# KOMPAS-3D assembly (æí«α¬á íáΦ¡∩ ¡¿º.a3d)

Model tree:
1. Смещенная плоскость:1
     Расстояние = 10
2. Скругление:1
     Радиус = 1
3. Условное изображение резьбы:1  (labels: Сплав АЛ8  ГОСТ 1583-93)
     Длина резьбы = 12; Шаг резьбы = 1.5; Номинальный диаметр резьбы = 12.6991; Расстояние = 10.004; Расстояние = 0.1

Referenced files in D:\МОДЕЛЬ ТАНКА Т90\ДЕТАЛИ\БАШНЯ\БАШНЯ ЛИТАЯ\: башня низ.m3d, Сборка орудие с маской.a3d, стопор орудия.m3d, серво.m3d, рычаг серво.m3d
Referenced files in D:\МОДЕЛЬ ТАНКА Т90\ДЕТАЛИ\ОБЩИЕ ДЕТАЛИ\: эл двигатель.m3d
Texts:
  Сборка башня низ
  stalker61
  Сплав АЛ8  ГОСТ 1583-93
